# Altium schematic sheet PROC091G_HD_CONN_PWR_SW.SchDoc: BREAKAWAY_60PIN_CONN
size 431 x 279 mm; Date: Not shown in title block; ApprovedBy: Not shown in title block; CheckedBy: Not shown in title block; Author: Not shown in title block; CompanyName: Not shown in title block; DrawnBy: Antony/Bala; Engineer: Not shown in title block; Organization: Not shown in title block; Address1: Not shown in title block; Address2: Not shown in title block; Address3: Not shown in title block; Address4: Not shown in title block; DocumentNumber: 7; Revision: Use project parameter SCH_Rev; SheetNumber: 7; SheetTotal: 12; PageSetup: Record=PageOptions¦CenterHorizontal=True¦CenterVertical=True¦PrintScale=1.00¦XCorrection=1.00¦YCorrection=1.00¦PrintKind=0¦BorderSize=5000000¦LeftOffset=0¦BottomOffset=0¦Orientation=2¦PaperLength=1000¦PaperWidth=1000¦Scale=100¦PaperSource=15¦PrintQuality=600¦MediaType=1¦DitherType=10¦PaperKind=Letter¦PrintScaleMode=1
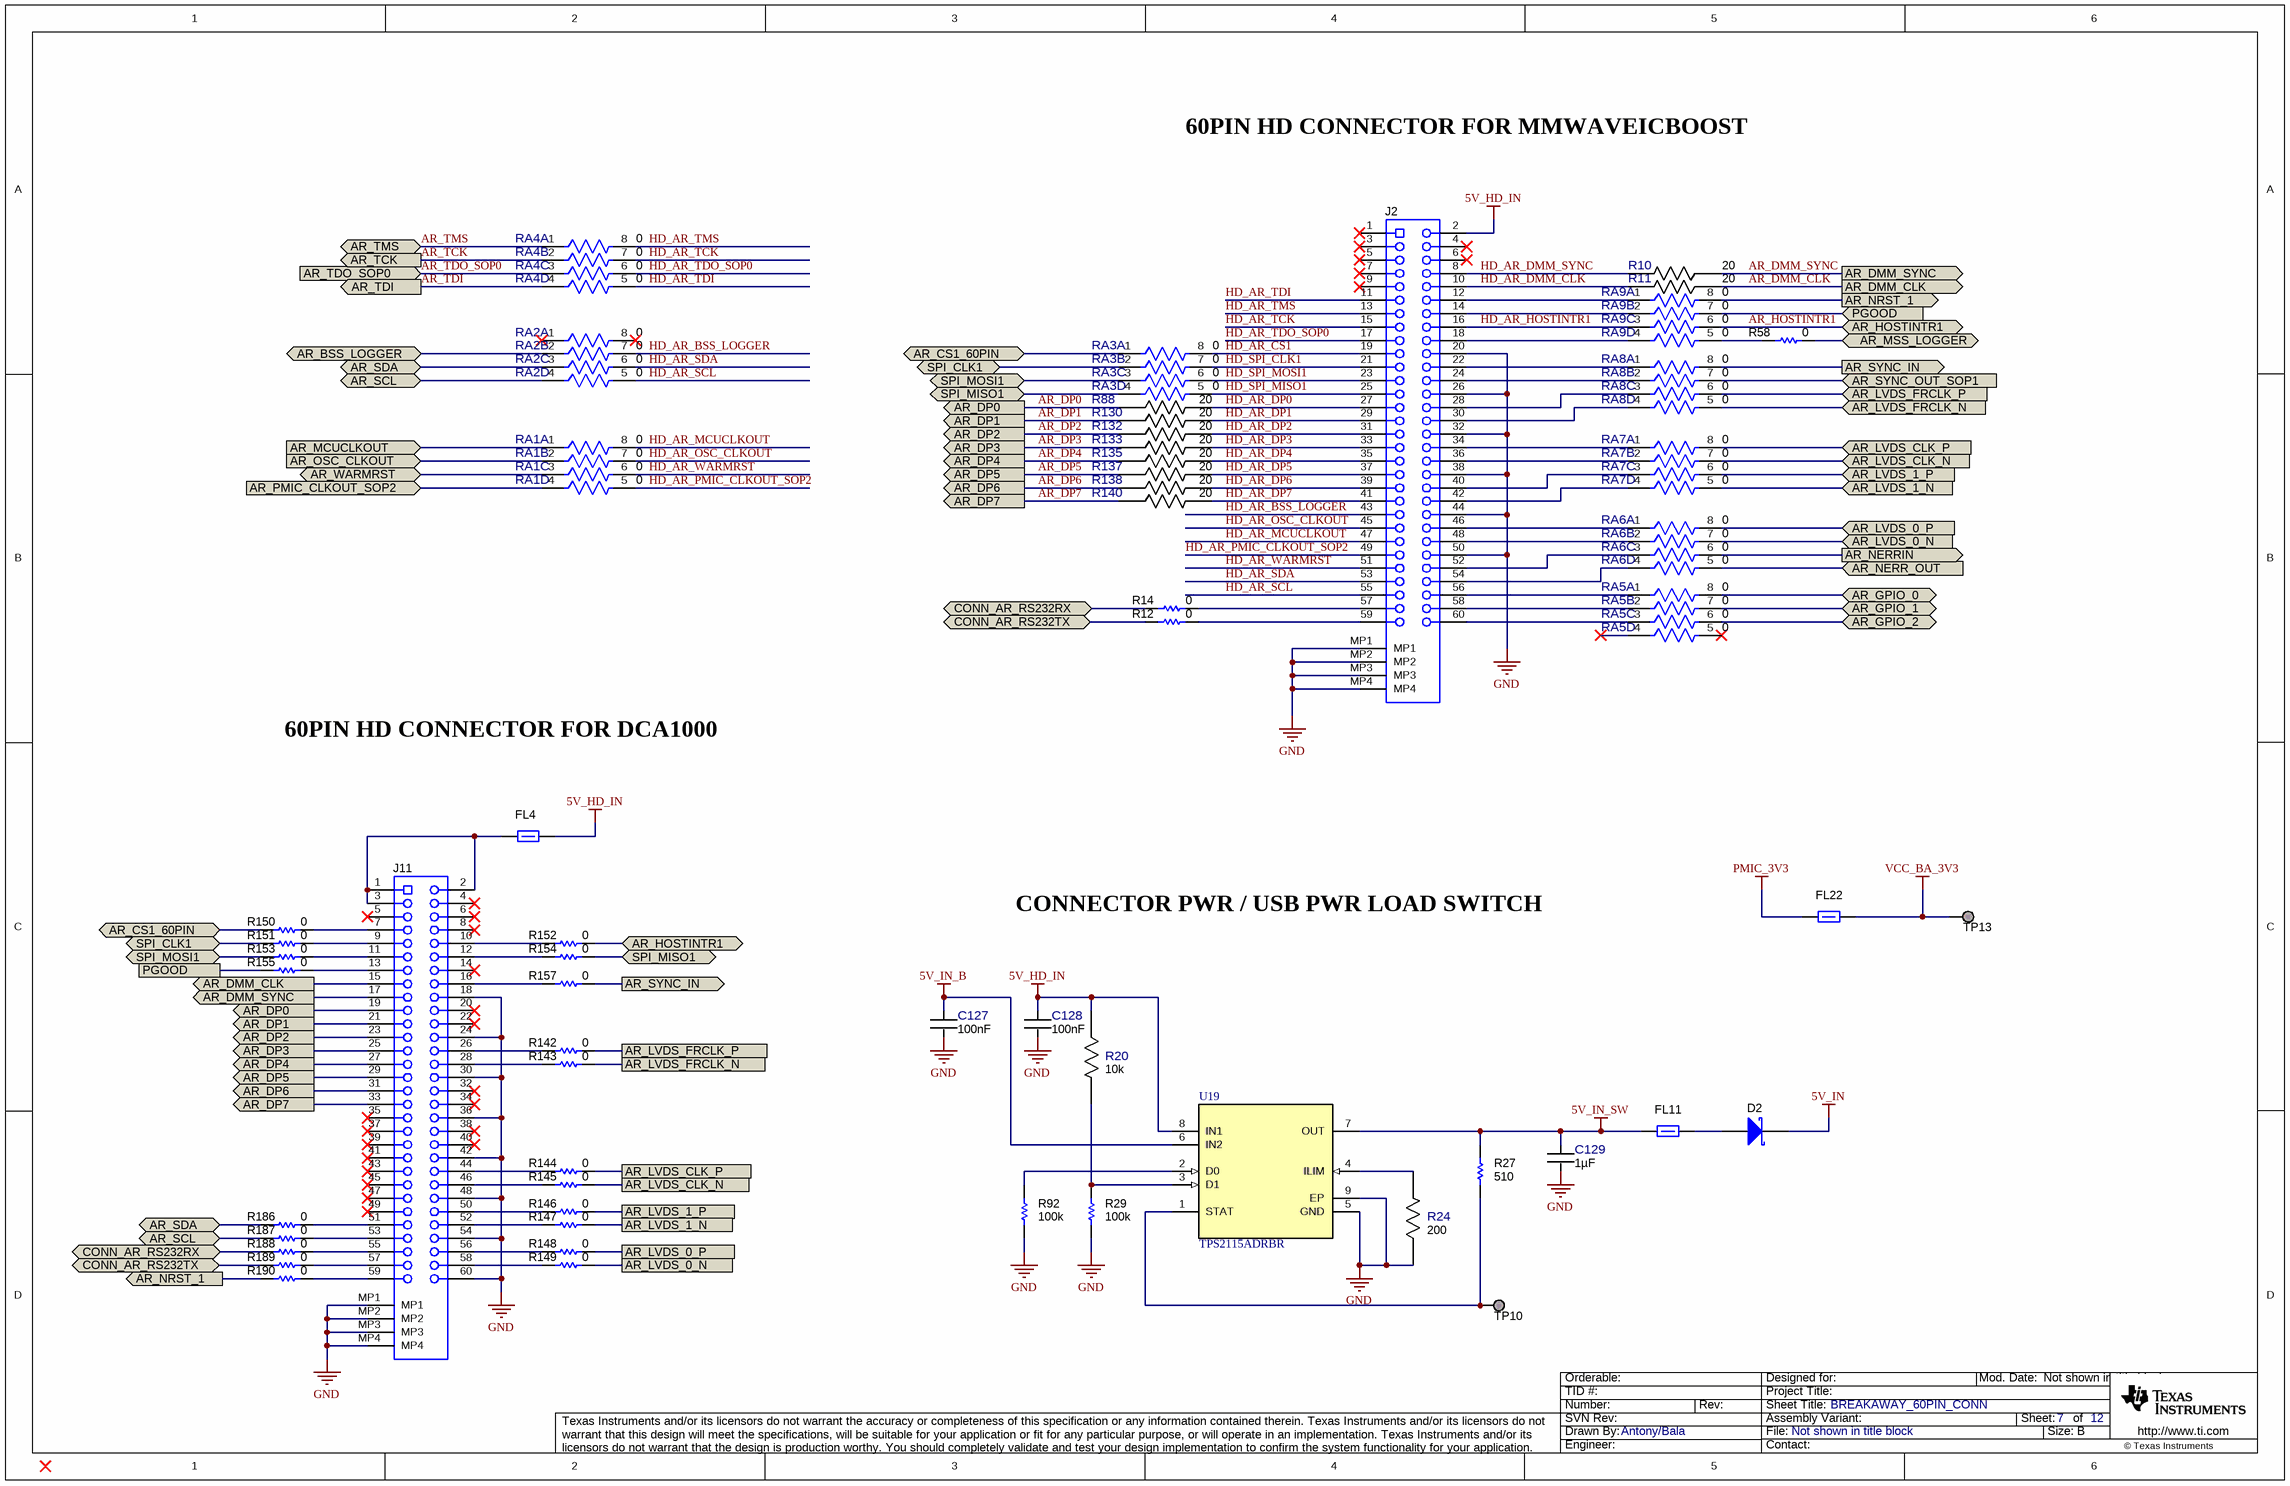
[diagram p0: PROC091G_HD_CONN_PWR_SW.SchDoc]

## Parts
C127  Cap_F: 100nF  [FP-GRM033R6YA104KE14D_0201 (0603 Metric)-IPC_C]  (hidden comment: GRM033R6YA104KE14D)
C128  Cap_F: 100nF  [FP-GRM033R6YA104KE14D_0201 (0603 Metric)-IPC_C]  (hidden comment: GRM033R6YA104KE14D)
C129  Cap_F: 1µF  [FP-CL03A105MO3NRNH_0201-IPC_C]  (hidden comment: CL03A105MO3NRNH)
D2  NSR20F30NXT5G  [DSN2_0603]  (value not drawn)
FL4  BLM15PD300SZ1D  [0402L]  (value not drawn)
FL11  BLM15PD300SZ1D  [0402L]  (value not drawn)
FL22  BLM15PD300SZ1D  [0402L]  (value not drawn)
J2  QSH-030-01-L-D-A  [Samtec_QSH-030-01-X-D-A]  (value not drawn)
J11  QSH-030-01-L-D-A  [Samtec_QSH-030-01-X-D-A]  (value not drawn)
R10  Res_ohm: 20  [FP-AC0201FR-0720RL_0201-IPC_C]  (hidden comment: AC0201FR-0720RL)
R11  Res_ohm: 20  [FP-AC0201FR-0720RL_0201-IPC_C]  (hidden comment: AC0201FR-0720RL)
R12  Res_ohm: 0  [FP-RC0201JR-070RL_0201 (0603 Metric)-MFG]  (hidden comment: RC0201JR-070RL)
R14  Res_ohm: 0  [FP-RC0201JR-070RL_0201 (0603 Metric)-MFG]  (hidden comment: RC0201JR-070RL)
R20  Res_ohm: 10k  [FP-RR0306P-103-D_0201-IPC_C]  (hidden comment: RR0306P-103-D)
R24  Res_ohm: 200  [FP-CRCW0402200RFKEDHP_0402-IPC_C]  (hidden comment: CRCW0402200RFKEDHP)
R27  value 510  [0201L]  (hidden comment: RC0201JR-07510RL)
R29  value 100k  [0201L]  (hidden comment: CRCW0201100KFKED)
R58  Res_ohm: 0  [FP-RC0201JR-070RL_0201 (0603 Metric)-MFG]  (hidden comment: RC0201JR-070RL)
R88  Res_ohm: 20  [FP-AC0201FR-0720RL_0201-IPC_C]  (hidden comment: AC0201FR-0720RL)
R92  value 100k  [0201L]  (hidden comment: CRCW0201100KFKED)
R130  Res_ohm: 20  [FP-AC0201FR-0720RL_0201-IPC_C]  (hidden comment: AC0201FR-0720RL)
R132  Res_ohm: 20  [FP-AC0201FR-0720RL_0201-IPC_C]  (hidden comment: AC0201FR-0720RL)
R133  Res_ohm: 20  [FP-AC0201FR-0720RL_0201-IPC_C]  (hidden comment: AC0201FR-0720RL)
R135  Res_ohm: 20  [FP-AC0201FR-0720RL_0201-IPC_C]  (hidden comment: AC0201FR-0720RL)
R137  Res_ohm: 20  [FP-AC0201FR-0720RL_0201-IPC_C]  (hidden comment: AC0201FR-0720RL)
R138  Res_ohm: 20  [FP-AC0201FR-0720RL_0201-IPC_C]  (hidden comment: AC0201FR-0720RL)
R140  Res_ohm: 20  [FP-AC0201FR-0720RL_0201-IPC_C]  (hidden comment: AC0201FR-0720RL)
R142  Res_ohm: 0  [FP-RC0201JR-070RL_0201 (0603 Metric)-MFG]  (hidden comment: RC0201JR-070RL)
R143  Res_ohm: 0  [FP-RC0201JR-070RL_0201 (0603 Metric)-MFG]  (hidden comment: RC0201JR-070RL)
R144  Res_ohm: 0  [FP-RC0201JR-070RL_0201 (0603 Metric)-MFG]  (hidden comment: RC0201JR-070RL)
R145  Res_ohm: 0  [FP-RC0201JR-070RL_0201 (0603 Metric)-MFG]  (hidden comment: RC0201JR-070RL)
R146  Res_ohm: 0  [FP-RC0201JR-070RL_0201 (0603 Metric)-MFG]  (hidden comment: RC0201JR-070RL)
R147  Res_ohm: 0  [FP-RC0201JR-070RL_0201 (0603 Metric)-MFG]  (hidden comment: RC0201JR-070RL)
R148  Res_ohm: 0  [FP-RC0201JR-070RL_0201 (0603 Metric)-MFG]  (hidden comment: RC0201JR-070RL)
R149  Res_ohm: 0  [FP-RC0201JR-070RL_0201 (0603 Metric)-MFG]  (hidden comment: RC0201JR-070RL)
R150  Res_ohm: 0  [FP-RC0201JR-070RL_0201 (0603 Metric)-MFG]  (hidden comment: RC0201JR-070RL)
R151  Res_ohm: 0  [FP-RC0201JR-070RL_0201 (0603 Metric)-MFG]  (hidden comment: RC0201JR-070RL)
R152  Res_ohm: 0  [FP-RC0201JR-070RL_0201 (0603 Metric)-MFG]  (hidden comment: RC0201JR-070RL)
R153  Res_ohm: 0  [FP-RC0201JR-070RL_0201 (0603 Metric)-MFG]  (hidden comment: RC0201JR-070RL)
R154  Res_ohm: 0  [FP-RC0201JR-070RL_0201 (0603 Metric)-MFG]  (hidden comment: RC0201JR-070RL)
R155  Res_ohm: 0  [FP-RC0201JR-070RL_0201 (0603 Metric)-MFG]  (hidden comment: RC0201JR-070RL)
R157  Res_ohm: 0  [FP-RC0201JR-070RL_0201 (0603 Metric)-MFG]  (hidden comment: RC0201JR-070RL)
R186  Res_ohm: 0  [FP-RC0201JR-070RL_0201 (0603 Metric)-MFG]  (hidden comment: RC0201JR-070RL)
R187  Res_ohm: 0  [FP-RC0201JR-070RL_0201 (0603 Metric)-MFG]  (hidden comment: RC0201JR-070RL)
R188  Res_ohm: 0  [FP-RC0201JR-070RL_0201 (0603 Metric)-MFG]  (hidden comment: RC0201JR-070RL)
R189  Res_ohm: 0  [FP-RC0201JR-070RL_0201 (0603 Metric)-MFG]  (hidden comment: RC0201JR-070RL)
R190  Res_ohm: 0  [FP-RC0201JR-070RL_0201 (0603 Metric)-MFG]  (hidden comment: RC0201JR-070RL)
RA1  Res_ohm: 0  [FP-EXB-18VR000X_0502-MFG]  (hidden comment: EXB-18VR000X)  (parts A,B,C,D of 4)
RA2  Res_ohm: 0  [FP-EXB-18VR000X_0502-MFG]  (hidden comment: EXB-18VR000X)  (parts A,B,C,D of 4)
RA3  Res_ohm: 0  [FP-EXB-18VR000X_0502-MFG]  (hidden comment: EXB-18VR000X)  (parts A,B,C,D of 4)
RA4  Res_ohm: 0  [FP-EXB-18VR000X_0502-MFG]  (hidden comment: EXB-18VR000X)  (parts A,B,C,D of 4)
RA5  Res_ohm: 0  [FP-EXB-18VR000X_0502-MFG]  (hidden comment: EXB-18VR000X)  (parts A,B,C,D of 4)
RA6  Res_ohm: 0  [FP-EXB-18VR000X_0502-MFG]  (hidden comment: EXB-18VR000X)  (parts A,B,C,D of 4)
RA7  Res_ohm: 0  [FP-EXB-18VR000X_0502-MFG]  (hidden comment: EXB-18VR000X)  (parts A,B,C,D of 4)
RA8  Res_ohm: 0  [FP-EXB-18VR000X_0502-MFG]  (hidden comment: EXB-18VR000X)  (parts A,B,C,D of 4)
RA9  Res_ohm: 0  [FP-EXB-18VR000X_0502-MFG]  (hidden comment: EXB-18VR000X)  (parts A,B,C,D of 4)
TP10  TESTPOINT  [TP_25MIL-SMT]  (value not drawn)  (no BOM)
TP13  TESTPOINT  [TP_25MIL-SMT]  (value not drawn)  (no BOM)
U19  TPS2115ADRBR  [DRB0008B]

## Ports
AR_BSS_LOGGER (bidir), AR_CS1_60PIN (bidir), AR_DMM_CLK (out), AR_DMM_SYNC (out), AR_DP0 (out), AR_DP1 (out), AR_DP2 (out), AR_DP3 (out), AR_DP4 (out), AR_DP5 (out), AR_DP6 (out), AR_DP7 (out), AR_GPIO_0 (bidir), AR_GPIO_1 (bidir), AR_GPIO_2 (bidir), AR_HOSTINTR1 (bidir), AR_LVDS_0_N, AR_LVDS_0_N (in), AR_LVDS_0_P, AR_LVDS_0_P (in), AR_LVDS_1_N, AR_LVDS_1_N (in), AR_LVDS_1_P, AR_LVDS_1_P (in), AR_LVDS_CLK_N, AR_LVDS_CLK_N (in), AR_LVDS_CLK_P, AR_LVDS_CLK_P (in), AR_LVDS_FRCLK_N, AR_LVDS_FRCLK_N (in), AR_LVDS_FRCLK_P, AR_LVDS_FRCLK_P (in), AR_MCUCLKOUT (in), AR_MSS_LOGGER (bidir), AR_NERR_OUT (in), AR_NERRIN (out), AR_NRST_1 (out), AR_OSC_CLKOUT (in), AR_PMIC_CLKOUT_SOP2 (in), AR_SCL (bidir), AR_SDA (bidir), AR_SYNC_IN (out), AR_SYNC_OUT_SOP1 (in), AR_TCK (out), AR_TDI (out), AR_TDO_SOP0 (in), AR_TMS (bidir), AR_WARMRST (bidir), CONN_AR_RS232RX (bidir), CONN_AR_RS232TX (bidir), PGOOD, PGOOD (in), SPI_CLK1 (bidir), SPI_MISO1 (bidir), SPI_MOSI1 (bidir)

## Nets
5V_HD_IN: C128.1 FL4.2 J2.2 R20.1 U19.8(IN1)
5V_IN: D2.1(K)
5V_IN_B: C127.1 U19.6(IN2)
5V_IN_SW: C129.1 FL11.1 R27.1 U19.7(OUT)
GND: C127.2 C128.2 C129.2 J2.20 J2.26 J2.32 J2.38 J2.44 J2.50 J2.MP1 J2.MP2 J2.MP3 J2.MP4 J11.18 J11.24 J11.30 J11.36 J11.42 J11.48 J11.54 J11.60 J11.MP1 J11.MP2 J11.MP3 J11.MP4 R24.1 R29.1 R92.2 U19.5(GND) U19.9(EP)
PMIC_3V3: FL22.1
VCC_BA_3V3: FL22.2 TP13.1
AR_BSS_LOGGER: RA2.2 ; port AR_BSS_LOGGER
AR_CS1_60PIN: R150.2 RA3.1 ; port AR_CS1_60PIN
AR_DMM_CLK: J11.15 R11.1 ; port AR_DMM_CLK
AR_DMM_SYNC: J11.17 R10.1 ; port AR_DMM_SYNC
AR_DP0: J11.19 R88.1 ; port AR_DP0
AR_DP1: J11.21 R130.1 ; port AR_DP1
AR_DP2: J11.23 R132.1 ; port AR_DP2
AR_DP3: J11.25 R133.1 ; port AR_DP3
AR_DP4: J11.27 R135.1 ; port AR_DP4
AR_DP5: J11.29 R137.1 ; port AR_DP5
AR_DP6: J11.31 R138.1 ; port AR_DP6
AR_DP7: J11.33 R140.1 ; port AR_DP7
AR_GPIO_0: RA5.8 ; port AR_GPIO_0
AR_GPIO_1: RA5.7 ; port AR_GPIO_1
AR_GPIO_2: RA5.6 ; port AR_GPIO_2
AR_HOSTINTR1: R152.1 RA9.6 ; port AR_HOSTINTR1
AR_LVDS_0_N: R149.1 RA6.7 ; port AR_LVDS_0_N
AR_LVDS_0_P: R148.1 RA6.8 ; port AR_LVDS_0_P
AR_LVDS_1_N: R147.1 RA7.5 ; port AR_LVDS_1_N
AR_LVDS_1_P: R146.1 RA7.6 ; port AR_LVDS_1_P
AR_LVDS_CLK_N: R145.1 RA7.7 ; port AR_LVDS_CLK_N
AR_LVDS_CLK_P: R144.1 RA7.8 ; port AR_LVDS_CLK_P
AR_LVDS_FRCLK_N: R143.1 RA8.5 ; port AR_LVDS_FRCLK_N
AR_LVDS_FRCLK_P: R142.1 RA8.6 ; port AR_LVDS_FRCLK_P
AR_MCUCLKOUT: RA1.1 ; port AR_MCUCLKOUT
AR_MSS_LOGGER: R58.1 ; port AR_MSS_LOGGER
AR_NERR_OUT: RA6.5 ; port AR_NERR_OUT
AR_NERRIN: RA6.6 ; port AR_NERRIN
AR_NRST_1: R190.2 RA9.8 ; port AR_NRST_1
AR_OSC_CLKOUT: RA1.2 ; port AR_OSC_CLKOUT
AR_PMIC_CLKOUT_SOP2: RA1.4 ; port AR_PMIC_CLKOUT_SOP2
AR_SCL: R187.2 RA2.4 ; port AR_SCL
AR_SDA: R186.2 RA2.3 ; port AR_SDA
AR_SYNC_IN: R157.1 RA8.8 ; port AR_SYNC_IN
AR_SYNC_OUT_SOP1: RA8.7 ; port AR_SYNC_OUT_SOP1
AR_TCK: RA4.2 ; port AR_TCK
AR_TDI: RA4.4 ; port AR_TDI
AR_TDO_SOP0: RA4.3 ; port AR_TDO_SOP0
AR_TMS: RA4.1 ; port AR_TMS
AR_WARMRST: RA1.3 ; port AR_WARMRST
CONN_AR_RS232RX: R14.2 R188.2 ; port CONN_AR_RS232RX
CONN_AR_RS232TX: R12.2 R189.2 ; port CONN_AR_RS232TX
HD_AR_BSS_LOGGER: J2.43 RA2.7
HD_AR_CS1: J2.19 RA3.8
HD_AR_DMM_CLK: J2.10 R11.2
HD_AR_DMM_SYNC: J2.8 R10.2
HD_AR_DP0: J2.27 R88.2
HD_AR_DP1: J2.29 R130.2
HD_AR_DP2: J2.31 R132.2
HD_AR_DP3: J2.33 R133.2
HD_AR_DP4: J2.35 R135.2
HD_AR_DP5: J2.37 R137.2
HD_AR_DP6: J2.39 R138.2
HD_AR_DP7: J2.41 R140.2
HD_AR_HOSTINTR1: J2.16 RA9.3
HD_AR_MCUCLKOUT: J2.47 RA1.8
HD_AR_OSC_CLKOUT: J2.45 RA1.7
HD_AR_PMIC_CLKOUT_SOP2: J2.49 RA1.5
HD_AR_SCL: J2.55 RA2.5
HD_AR_SDA: J2.53 RA2.6
HD_AR_TCK: J2.15 RA4.7
HD_AR_TDI: J2.11 RA4.5
HD_AR_TDO_SOP0: J2.17 RA4.6
HD_AR_TMS: J2.13 RA4.8
HD_AR_WARMRST: J2.51 RA1.6
HD_SPI_CLK1: J2.21 RA3.7
HD_SPI_MISO1: J2.25 RA3.5
HD_SPI_MOSI1: J2.23 RA3.6
PGOOD: R155.2 RA9.7 ; port PGOOD
SPI_CLK1: R151.2 RA3.2 ; port SPI_CLK1
SPI_MISO1: R154.1 RA3.4 ; port SPI_MISO1
SPI_MOSI1: R153.2 RA3.3 ; port SPI_MOSI1
NetD2_2: D2.2(A) FL11.2
NetFL4_1: FL4.1 J11.1 J11.2 J11.3
NetJ2_12: J2.12 RA9.1
NetJ2_14: J2.14 RA9.2
NetJ2_18: J2.18 RA9.4
NetJ2_22: J2.22 RA8.1
NetJ2_24: J2.24 RA8.2
NetJ2_28: J2.28 RA8.3
NetJ2_30: J2.30 RA8.4
NetJ2_34: J2.34 RA7.1
NetJ2_36: J2.36 RA7.2
NetJ2_40: J2.40 RA7.3
NetJ2_42: J2.42 RA7.4
NetJ2_46: J2.46 RA6.1
NetJ2_48: J2.48 RA6.2
NetJ2_52: J2.52 RA6.3
NetJ2_54: J2.54 RA6.4
NetJ2_56: J2.56 RA5.1
NetJ2_57: J2.57 R14.1
NetJ2_58: J2.58 RA5.2
NetJ2_59: J2.59 R12.1
NetJ2_60: J2.60 RA5.3
NetJ11_7: J11.7 R150.1
NetJ11_9: J11.9 R151.1
NetJ11_10: J11.10 R152.2
NetJ11_11: J11.11 R153.1
NetJ11_12: J11.12 R154.2
NetJ11_13: J11.13 R155.1
NetJ11_16: J11.16 R157.2
NetJ11_26: J11.26 R142.2
NetJ11_28: J11.28 R143.2
NetJ11_44: J11.44 R144.2
NetJ11_46: J11.46 R145.2
NetJ11_50: J11.50 R146.2
NetJ11_51: J11.51 R186.1
NetJ11_52: J11.52 R147.2
NetJ11_53: J11.53 R187.1
NetJ11_55: J11.55 R188.1
NetJ11_56: J11.56 R148.2
NetJ11_57: J11.57 R189.1
NetJ11_58: J11.58 R149.2
NetJ11_59: J11.59 R190.1
NetR20_2: R20.2 R29.2 U19.3(D1)
NetR24_2: R24.2 U19.4(ILIM)
NetR27_2: R27.2 TP10.1 U19.1(STAT)
NetR58_2: R58.2 RA9.5
NetR92_1: R92.1 U19.2(D0)

Not connected (* = marked no-connect by the designer): J2 1* 3* 4* 5* 6* 7* 9*; J11 4* 5* 6* 8* 14* 20* 22* 32* 34* 35* 37* 38* 39* 40* 41* 43* 45* 47* 49*; RA2 1* 8*; RA5 4* 5*

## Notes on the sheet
- 60PIN HD CONNECTOR FOR MMWAVEICBOOST
- 60PIN HD CONNECTOR FOR DCA1000
- CONNECTOR PWR / USB PWR LOAD SWITCH

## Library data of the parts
C127 C128 = CMP-0086440-1: Cap Ceramic 0.1uF 35V X5R 10% Pad SMD 0201 85C T/R; Manufacturer: Murata Electronics North America; AEC Qualified: No; SizeZ_mm: 0.33mm; Symbol Name: SYM-GRM033R6YA104KE14D; TempCo: 15%
C129 = CMP-0086446-1: 1µF ±20% 16V Ceramic Capacitor X5R 0201; Manufacturer: Samsung Electro-Mechanics; AEC Qualified: No; SizeZ_mm: 0.39mm; Symbol Name: SYM-CL03A105MO3NRNH; TempCo: 15%
D2 = CMP-0028829-2: Diode, Schottky, 30 V, 2 A, 2-XFDFN; Manufacturer: ON Semiconductor; Value2: 0.48V; SizeY_mm: 0.8; Value: 30V; TJmax_C: 150°C; Green_Lifecycle: Not Set; SizeAreaWB_mm2: 4.68; Value1: 2A; SizeArea_mm2: 1.28; Green_REACh: Incomplete; AEC Category: Q101; SizeZ_mm: 0.31; Vf_V: 480mV; AEC Qualified: N; SizeX_mm: 1.6
FL4 FL11 FL22 = CMP-0078934-1: Inductor, Ferrite Bead, Ferrite, 2.2 A, 0.035 ohm, AEC-Q200 Grade 1, SMD; Manufacturer: MuRata; AEC Category: Q200; AEC Grade: 1; AEC Qualified: Y; DCR_ohm: 0.035; Imax_A: 2.2A; SizeArea_mm2: 0.5; SizeAreaWB_mm2: 3; SizeZ_mm: 0.6
J2 J11 = CMP-0075524-1: Receptacle, 0.5 mm, 30x2, Gold, TH; Manufacturer: Samtec; Pitch_mm: 0.5; Gender: Female; Green_REACh: Passed; CT: False; Shrouded: N; RowSpacing_mm: 5.73; Green_Lifecycle: Active; Row_Count: 2
R10 R11 R88 R130 R132 R133 R135 R137 R138 R140 = CMP-0087185-1: RES SMD 20 OHM 1% 1/20W 0201; Manufacturer: Yageo; AEC Grade: Grade 0; AEC Qualified: Yes; Power_W: 50mW; SizeZ_mm: 0.26mm; Symbol Name: SYM-AC0201FR-0720RL; TempCo: 200ppm/°C; VDC_V: 25V
R12 R14 R58 R142-R155 R157 R186-R190 = CMP-0086442-2: RES SMD 0 OHM JUMPER 1/20W 0201; Manufacturer: Yageo; AEC Qualified: No; Power_W: 50mW; SizeZ_mm: 0.26mm; TempCo: 200ppm/°C; Tolerance_%: 5%; VDC_V: 25V
R20 = CMP-0088002-1: 10 kOhms ±0.5% 0.05W, 1/20W Chip Resistor 0201 (0603 Metric)  Thin Film; Manufacturer: Susumu; AEC Qualified: No; Power_W: 50mW; SizeZ_mm: 0.26mm; Symbol Name: SYM-RR0306P-103-D; TempCo: 25ppm/°C; VDC_V: 15V
R24 = CMP-0087183-1: RES SMD 200 OHM 1% 1/5W 0402; Manufacturer: Vishay Dale; AEC Grade: Grade 0; AEC Qualified: Yes; Power_W: 200mW; SizeZ_mm: 0.4mm; Symbol Name: SYM-CRCW0402200RFKEDHP; TempCo: 100ppm/°C; VDC_V: 50V
R27 = CMP-0027137-1: RES, 510, 5%, 0.05 W, 0201; Manufacturer: Yageo America; AEC Category: Q200; AEC Qualified: N; EIA_Code: E24; Power_W: 50mW; SizeArea_mm2: 0.18; SizeX_mm: 0.6; SizeY_mm: 0.3; SizeZ_mm: 0.26; TempCo: 200 ppm/C; U/M: EA; Value2: 0.05W; Value_Code: 510R; VDC_V: 25V
R29 R92 = CMP-0027261-3: RES, 100 k, 1%, 0.05 W, 0201; Manufacturer: Vishay-Dale; AEC Category: Q200; AEC Qualified: N; EIA_Code: E96; Power_W: 50mW; SizeArea_mm2: 0.18; SizeX_mm: 0.6; SizeY_mm: 0.3; SizeZ_mm: 0.26; TempCo: 100 ppm/C; Value2: 0.05W; VDC_V: 30V
RA1-RA9 = CMP-0087186-1: RES ARRAY 4 RES ZERO OHM 0502; Manufacturer: Panasonic Electronic Components; AEC Qualified: No; Power_W: 100mW; SizeZ_mm: 0.45mm; TempCo: -200/+600ppm/°C; Tolerance_%: 5%; VDC_V: 12.5V
TP10 TP13 = CMP-0078143-3: TEST POINT.  No entry in BOM.
U19 = CMP-0043358-3: Dual In / Single Out Autoswitching Power Mux, 2.8 to 5.5 V, -40 to 85 degC, 8-pin SON (DRB), Green (RoHS & no Sb/Br); Manufacturer: Texas Instruments; AEC Category: Q200; AEC Qualified: N; CompType: IC; IN1, IN2 Input Voltage(Max)(V): 5.5; IN1, IN2 Input Voltage(Min)(V): 2.8; IN1 Output Current(Max)(A): 1.25; IN1 rDS(on)(Typ)(mOhm): 84; IN2 rDS(on)(Typ)(Ohms): 0.084; Number of Inputs: 2; SizeArea_mm2: 9.0; SizeAreaWB_mm2: 16.0; SizeX_mm: 3.0; SizeZ_mm: 1.0; SubFamily: Power Multiplexer (MUX)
